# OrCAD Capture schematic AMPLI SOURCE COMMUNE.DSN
size A; title: Ampli NMOS à source commune; company: ULB BEAMS ELEC-H402
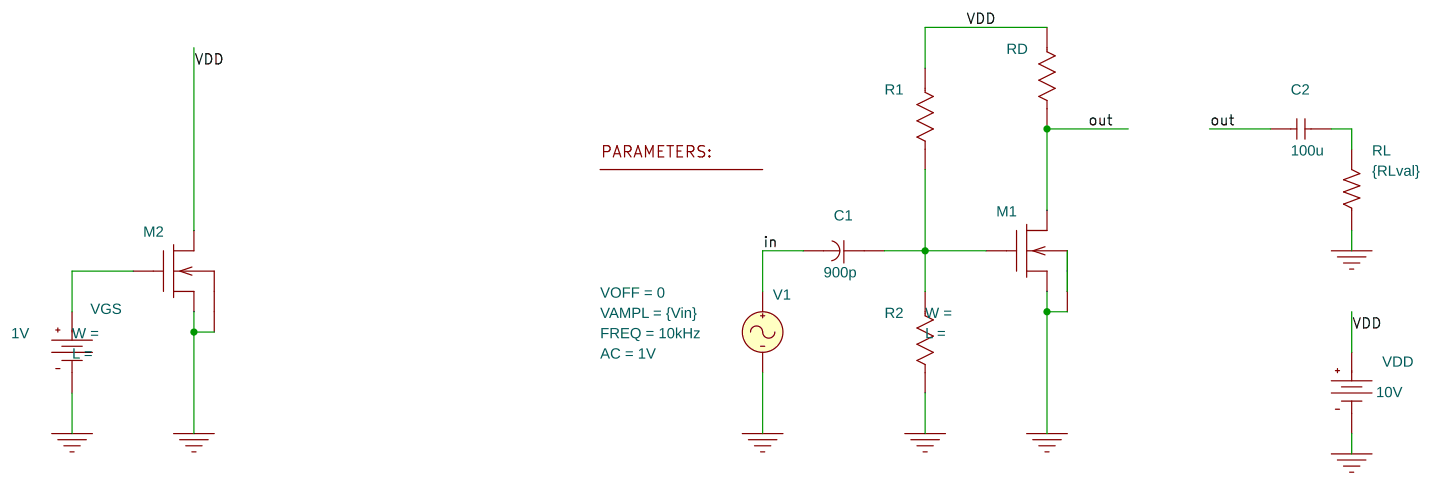
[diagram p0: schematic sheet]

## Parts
1  PARAM
C1  900p  [DIPCAP]
C2  100u  [RAD/CK05]
M1  NMOS
M2  NMOS
R1  ???
R2  ???
RD  ???
RL  {RLval}  [AX/RC05]
V1  VSIN
VDD  VDC
VGS  VDC

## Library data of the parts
1 = PARAM: RLval: 1000Meg; Vin: 1V
C1 = CAPACITOR
C2 = C
M1 M2 = NMOS
R1 R2 RD = RESISTOR
RL = R
V1 = VSIN: AC: 1V; FREQ: 10kHz; VAMPL: {Vin}; VOFF: 0
VDD = VDC: DC: 10V
VGS = VDC: DC: 1V

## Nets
VDD: M2.2(d) R1.2(B) RD.2(B) VDD.0(+)
0: M1.0(s) M1.4(b) M2.0(s) M2.4(b) R2.1(A) RL.1 V1.2(-) VDD.1(-) VGS.1(-)
in: C1.2(B) V1.1(+)
out: C2.1 M1.2(d) RD.1(A)
N14456: C1.1(A) M1.1(g) R1.1(A) R2.2(B)
N18848: C2.2 RL.2
N20556: M2.1(g) VGS.0(+)
